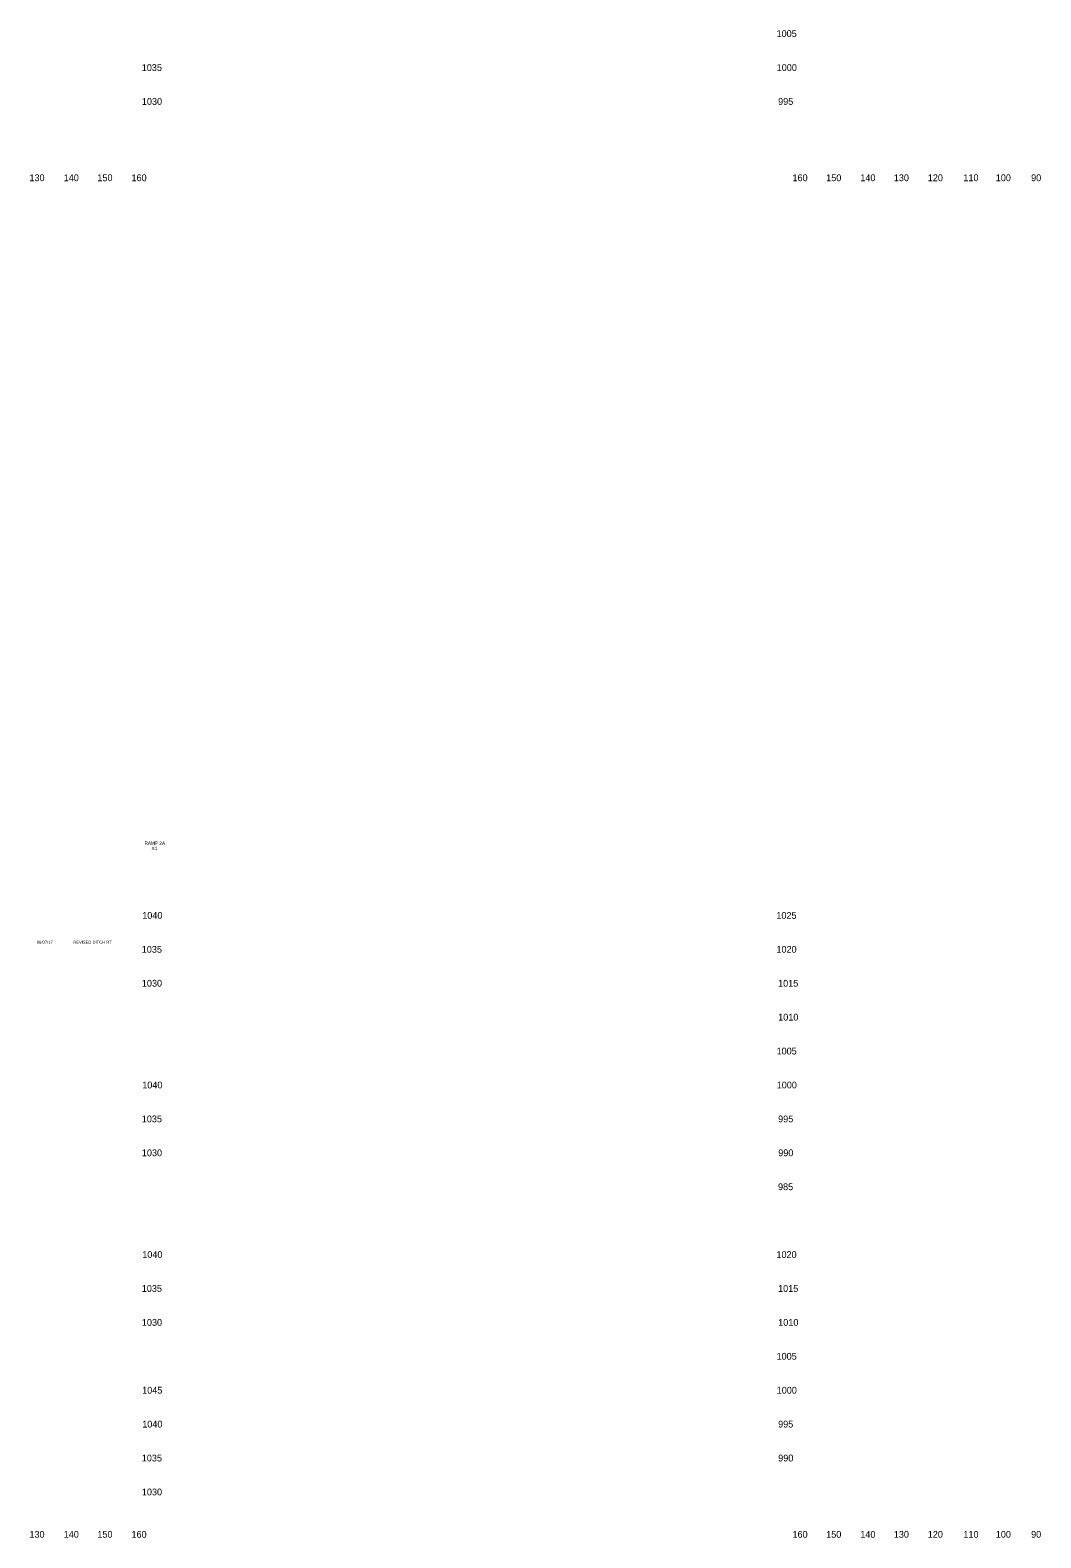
# Model space of a CAD drawing. Extents: x 4994 to 7388, y 4997 to 8804.
# Drawn here: x 5288.2 to 5586.4, y 4997.5 to 5442 of the extents above; entities that cross this region are included whole.
import ezdxf

# ---------------------------------------------------------------- set-up
doc = ezdxf.new("R2010")
doc.units = 0
for name, color, linetype in [('RD_SHT_ID', 7, 'Continuous'), ('RD_SHT_TX', 7, 'Continuous'), ('RD_XS_TX_Offset', 7, 'Continuous')]:
    doc.layers.add(name, color=color, linetype=linetype)

msp = doc.modelspace()

# ---------------------------------------------------------------- texts
at = {"layer": 'RD_SHT_ID'}
for s, p in [('RAMP 2A', (5321.93, 5201.8)), ('X1', (5324.02, 5200.3))]:
    msp.add_text(s, height=1, dxfattribs=at).set_placement(p)
at = {"layer": 'RD_SHT_TX'}
for s, p in [('06/07/17', (5290.15, 5172.65)), ('REVISED DITCH RT', (5300.92, 5172.65))]:
    msp.add_text(s, height=0.88, dxfattribs=at).set_placement(p)
at = {"layer": 'RD_XS_TX_Offset'}
for s, p in [('1005', (5508.4, 5440)), ('1035', (5321.13, 5430)), ('1000', (5508.44, 5430)), ('1030', (5321.16, 5420)), ('995', (5508.86, 5420)), ('130', (5287.99, 5397.5)), ('140', (5298.1, 5397.5)), ('150', (5308.04, 5397.5)), ('160', (5318.1, 5397.5)), ('160', (5513.1, 5397.5)), ('150', (5523.04, 5397.5)), ('140', (5533.1, 5397.5)), ('130', (5542.99, 5397.5)), ('120', (5553.01, 5397.5)), ('110', (5563.51, 5397.5)), ('100', (5573.07, 5397.5)), ('90', (5583.5, 5397.5)), ('1040', (5321.27, 5180)), ('1025', (5508.34, 5180)), ('1035', (5321.13, 5170)), ('1020', (5508.37, 5170)), ('1030', (5321.16, 5160)), ('1015', (5508.85, 5160)), ('1010', (5508.88, 5150)), ('1005', (5508.4, 5140)), ('1040', (5321.27, 5130)), ('1000', (5508.44, 5130)), ('1035', (5321.13, 5120)), ('995', (5508.86, 5120)), ('1030', (5321.16, 5110)), ('990', (5508.89, 5110)), ('985', (5508.83, 5100)), ('1040', (5321.27, 5080)), ('1020', (5508.37, 5080)), ('1035', (5321.13, 5070)), ('1015', (5508.85, 5070)), ('1030', (5321.16, 5060)), ('1010', (5508.88, 5060)), ('1005', (5508.4, 5050)), ('1045', (5321.24, 5040)), ('1000', (5508.44, 5040)), ('1040', (5321.27, 5030)), ('995', (5508.86, 5030)), ('1035', (5321.13, 5020)), ('990', (5508.89, 5020)), ('1030', (5321.16, 5010)), ('130', (5287.99, 4997.5)), ('140', (5298.1, 4997.5)), ('150', (5308.04, 4997.5)), ('160', (5318.1, 4997.5)), ('160', (5513.1, 4997.5)), ('150', (5523.04, 4997.5)), ('140', (5533.1, 4997.5)), ('130', (5542.99, 4997.5)), ('120', (5553.01, 4997.5)), ('110', (5563.51, 4997.5)), ('100', (5573.07, 4997.5)), ('90', (5583.5, 4997.5))]:
    msp.add_text(s, height=2, dxfattribs=at).set_placement(p)

doc.saveas('drawing.dxf')
